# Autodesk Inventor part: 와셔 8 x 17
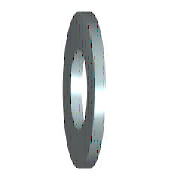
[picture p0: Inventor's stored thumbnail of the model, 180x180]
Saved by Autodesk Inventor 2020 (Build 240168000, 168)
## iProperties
Created: 2012-02
Part Number: 와셔 8 x 17
Material: 강철, 연강
Description: 평면 와셔
Document SubType Name: Modeling
Standard: KS B 1326
Designer: mduedu
Standards Organization: KS
Language: ko-KR
Size Designation: 8x17
Categories: <MemberInstance><Categories><Category DisplayName="조임쇠" InternalName="e4da775c-781d-43d5-af7c-5136215cf5a6" Mnemonic="FSTN"><Category DisplayName="와셔" InternalN
Density: 7.86 g/cm^3
Mass: 2.15757 g
Surface Area: 4.70799 cm^2
Volume: 0.2745 cm^3
Appearance: 주황색
IsCustomPart: 1
Author: mduedu
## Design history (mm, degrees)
sketch "스케치"
  geometry: C1 r 8.5 at (0, 0); C2 r 4.2 at (0, 0); 1 further point
  constraints: 2 centre point, 2 coincident
  dimensions: "d0" = 8.4 diameter of C2 (= SD1); "d1" = 17 diameter of C1 (= SD2)
extrude "본체" new body sketch "스케치" distance "d2" = 1.6 (= SD); taper "d3" = 0 deg
workaxis "Work Axis1"
workplane "Work Plane1"
body "Solid1"
other parameters: "SD1" = 8.4 [user parameter; used in 1 equation term], "SD2" = 17 [user parameter; used in 1 equation term], "SD" = 1.6 [user parameter; used in 1 equation term], "d4" = 0, "d5" = 0, "d6" = 0, "d7" = 0, "NND" = 8 [user parameter]
